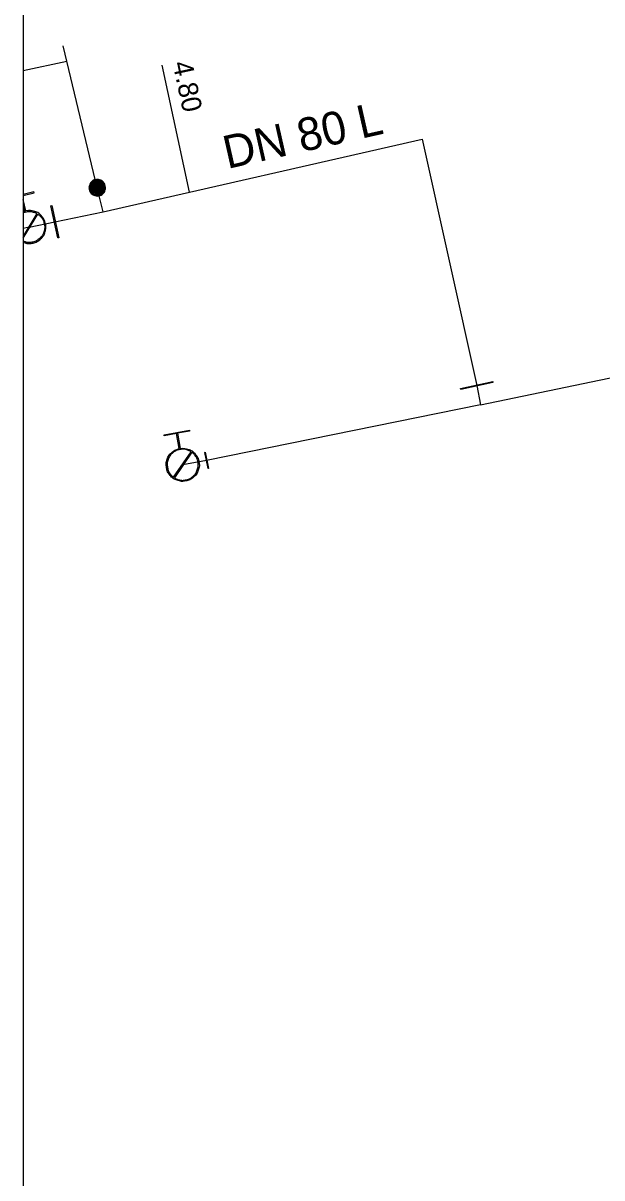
# Model space of a CAD drawing. Extents: x -820257 to -819974, y -1070894 to -1070484.
# Drawn here: x -820256.8 to -820221.7, y -1070621.8 to -1070551.7 of the extents above; entities that cross this region are included whole.
import ezdxf

# ---------------------------------------------------------------- set-up
doc = ezdxf.new("R2010")
doc.units = 0
for name, color, linetype in [('Default', 7, 'Continuous'), ('Hyd-odbočka', 7, 'Continuous'), ('Hyd-šoupě', 7, 'Continuous'), ('Hydrant', 7, 'Continuous'), ('Oměrka vodovodu', 7, 'Continuous'), ('Oměrka-text', 7, 'Continuous'), ('Přípojka vodovodu', 7, 'Continuous'), ('Přípojkový uzávěr', 7, 'Continuous'), ('Roz-řad', 7, 'Continuous'), ('Roz-řad-popis základní', 7, 'Continuous'), ('Řad-šoupě', 7, 'Continuous')]:
    doc.layers.add(name, color=color, linetype=linetype)

msp = doc.modelspace()

# ---------------------------------------------------------------- linework, layer by layer
at = {"layer": 'Default'}
msp.add_lwpolyline([(-819975.603, -1070484.403), (-820256.81, -1070484.403), (-820256.81, -1070893.932)], dxfattribs=at)
at = {"layer": 'Hyd-odbočka'}
msp.add_line((-820245.669, -1070578.217), (-820247.12, -1070578.483), dxfattribs=at)
at = {"layer": 'Hyd-šoupě'}
msp.add_lwpolyline([(-820245.752, -1070577.723), (-820245.553, -1070578.703), (-820245.584, -1070578.709), (-820245.782, -1070577.729), (-820245.752, -1070577.723)], dxfattribs=at)
at = {"layer": 'Hydrant'}
for p, q in [((-820256.81, -1070562.082), (-820256.81, -1070562.146)), ((-820256.644, -1070563.071), (-820256.81, -1070562.385)), ((-820256.81, -1070562.385), (-820256.81, -1070562.65)), ((-820256.81, -1070562.65), (-820256.704, -1070563.085)), ((-820256.81, -1070563.121), (-820256.81, -1070563.19)), ((-820255.975, -1070563.232), (-820256.81, -1070564.601)), ((-820256.81, -1070564.72), (-820255.924, -1070563.264)), ((-820256.81, -1070564.601), (-820256.81, -1070564.72)), ((-820256.81, -1070564.913), (-820256.81, -1070564.981))]:
    msp.add_line(p, q, dxfattribs=at)
for points in [[(-820256.81, -1070562.146), (-820256.136, -1070561.983), (-820256.151, -1070561.922), (-820256.81, -1070562.082)], [(-820247.332, -1070577.505), (-820247.502, -1070576.583), (-820248.239, -1070576.718), (-820248.25, -1070576.657), (-820246.714, -1070576.374), (-820246.702, -1070576.436), (-820247.44, -1070576.571), (-820247.27, -1070577.493)], [(-820247.678, -1070579.239), (-820246.612, -1070577.692)], [(-820246.562, -1070577.727), (-820247.628, -1070579.275)]]:
    msp.add_lwpolyline(points, dxfattribs=at)
for points, degree in [([(-820256.81, -1070564.981), (-820256.765, -1070564.998), (-820256.718, -1070565.011), (-820256.455, -1070565.083), (-820256.203, -1070565.022), (-820255.95, -1070564.961), (-820255.75, -1070564.776), (-820255.549, -1070564.592), (-820255.477, -1070564.329), (-820255.405, -1070564.067), (-820255.467, -1070563.814), (-820255.528, -1070563.56), (-820255.716, -1070563.358), (-820255.903, -1070563.157), (-820256.165, -1070563.087), (-820256.412, -1070563.023), (-820256.644, -1070563.071)], 3), ([(-820256.704, -1070563.085), (-820256.758, -1070563.1), (-820256.81, -1070563.121)], 2), ([(-820256.81, -1070563.19), (-820256.737, -1070563.158), (-820256.659, -1070563.139), (-820256.43, -1070563.083), (-820256.183, -1070563.148), (-820256.073, -1070563.178), (-820255.975, -1070563.232)], 3), ([(-820255.924, -1070563.264), (-820255.837, -1070563.321), (-820255.762, -1070563.401), (-820255.585, -1070563.59), (-820255.527, -1070563.829), (-820255.47, -1070564.066), (-820255.537, -1070564.312), (-820255.604, -1070564.557), (-820255.792, -1070564.73), (-820255.98, -1070564.904), (-820256.217, -1070564.961), (-820256.455, -1070565.019), (-820256.701, -1070564.95), (-820256.757, -1070564.935), (-820256.81, -1070564.913)], 3), ([(-820247.27, -1070577.493), (-820247.037, -1070577.458), (-820246.794, -1070577.537), (-820246.536, -1070577.62), (-820246.36, -1070577.832), (-820246.184, -1070578.044), (-820246.137, -1070578.302), (-820246.09, -1070578.557), (-820246.176, -1070578.815), (-820246.263, -1070579.074), (-820246.474, -1070579.246), (-820246.684, -1070579.419), (-820246.94, -1070579.466), (-820247.195, -1070579.513), (-820247.453, -1070579.426), (-820247.711, -1070579.34), (-820247.884, -1070579.129), (-820248.057, -1070578.919), (-820248.104, -1070578.663), (-820248.151, -1070578.406), (-820248.062, -1070578.145), (-820247.973, -1070577.885), (-820247.762, -1070577.715), (-820247.565, -1070577.555), (-820247.332, -1070577.505)], 3), ([(-820246.612, -1070577.692), (-820246.707, -1070577.632), (-820246.815, -1070577.596), (-820247.057, -1070577.518), (-820247.29, -1070577.561), (-820247.522, -1070577.603), (-820247.721, -1070577.763), (-820247.92, -1070577.923), (-820248.004, -1070578.166), (-820248.087, -1070578.41), (-820248.042, -1070578.652), (-820247.998, -1070578.892), (-820247.835, -1070579.089), (-820247.766, -1070579.175), (-820247.678, -1070579.239)], 3), ([(-820247.628, -1070579.275), (-820247.538, -1070579.332), (-820247.433, -1070579.366), (-820247.191, -1070579.449), (-820246.951, -1070579.405), (-820246.711, -1070579.36), (-820246.513, -1070579.198), (-820246.316, -1070579.036), (-820246.235, -1070578.794), (-820246.154, -1070578.553), (-820246.198, -1070578.313), (-820246.243, -1070578.071), (-820246.408, -1070577.873), (-820246.479, -1070577.789), (-820246.562, -1070577.727)], 3)]:
    msp.add_open_spline(points, degree=degree, dxfattribs=at)
at = {"layer": 'Oměrka vodovodu'}
for p, q in [((-820256.81, -1070554.555), (-820254.152, -1070553.993)), ((-820246.715, -1070561.929), (-820248.369, -1070554.217))]:
    msp.add_line(p, q, dxfattribs=at)
at = {"layer": 'Přípojka vodovodu'}
msp.add_lwpolyline([(-820251.957, -1070563.123), (-820252.308, -1070561.665), (-820254.38, -1070553.046)], dxfattribs=at)
at = {"layer": 'Přípojkový uzávěr'}
for points in [[(-820251.822, -1070561.548), (-820251.792, -1070561.67), (-820251.827, -1070561.802), (-820251.862, -1070561.933), (-820251.963, -1070562.027), (-820252.064, -1070562.121), (-820252.192, -1070562.152), (-820252.318, -1070562.182), (-820252.449, -1070562.146), (-820252.58, -1070562.109), (-820252.672, -1070562.009), (-820252.764, -1070561.908), (-820252.794, -1070561.782), (-820252.824, -1070561.656), (-820252.788, -1070561.525), (-820252.752, -1070561.393), (-820252.652, -1070561.301), (-820252.552, -1070561.21), (-820252.425, -1070561.179), (-820252.298, -1070561.149), (-820252.165, -1070561.186), (-820252.033, -1070561.223), (-820251.942, -1070561.324), (-820251.852, -1070561.425), (-820251.822, -1070561.548)], [(-820251.868, -1070561.559), (-820251.894, -1070561.448), (-820251.976, -1070561.356), (-820252.058, -1070561.264), (-820252.179, -1070561.231), (-820252.299, -1070561.197), (-820252.414, -1070561.225), (-820252.529, -1070561.252), (-820252.62, -1070561.335), (-820252.71, -1070561.418), (-820252.743, -1070561.538), (-820252.776, -1070561.657), (-820252.749, -1070561.771), (-820252.721, -1070561.886), (-820252.638, -1070561.977), (-820252.554, -1070562.068), (-820252.436, -1070562.101), (-820252.317, -1070562.133), (-820252.203, -1070562.106), (-820252.087, -1070562.078), (-820251.995, -1070561.993), (-820251.904, -1070561.908), (-820251.872, -1070561.789), (-820251.841, -1070561.67), (-820251.868, -1070561.559)], [(-820251.901, -1070561.567), (-820251.876, -1070561.67), (-820251.905, -1070561.78), (-820251.934, -1070561.889), (-820252.019, -1070561.968), (-820252.104, -1070562.047), (-820252.21, -1070562.073), (-820252.316, -1070562.098), (-820252.426, -1070562.068), (-820252.536, -1070562.038), (-820252.613, -1070561.953), (-820252.69, -1070561.869), (-820252.715, -1070561.763), (-820252.741, -1070561.657), (-820252.711, -1070561.547), (-820252.68, -1070561.437), (-820252.596, -1070561.36), (-820252.512, -1070561.283), (-820252.406, -1070561.258), (-820252.3, -1070561.232), (-820252.188, -1070561.263), (-820252.077, -1070561.294), (-820252.001, -1070561.379), (-820251.925, -1070561.464), (-820251.901, -1070561.567)], [(-820251.944, -1070561.577), (-820251.98, -1070561.425), (-820252.112, -1070561.345), (-820252.245, -1070561.264), (-820252.396, -1070561.301), (-820252.547, -1070561.337), (-820252.628, -1070561.47), (-820252.709, -1070561.602), (-820252.673, -1070561.752), (-820252.636, -1070561.904), (-820252.504, -1070561.985), (-820252.372, -1070562.066), (-820252.221, -1070562.03), (-820252.069, -1070561.994), (-820251.988, -1070561.862), (-820251.907, -1070561.73), (-820251.944, -1070561.577)], [(-820251.988, -1070561.587), (-820251.956, -1070561.721), (-820252.027, -1070561.836), (-820252.098, -1070561.951), (-820252.231, -1070561.983), (-820252.363, -1070562.015), (-820252.479, -1070561.944), (-820252.594, -1070561.873), (-820252.626, -1070561.741), (-820252.658, -1070561.608), (-820252.587, -1070561.492), (-820252.516, -1070561.377), (-820252.384, -1070561.345), (-820252.252, -1070561.313), (-820252.136, -1070561.384), (-820252.02, -1070561.454), (-820251.988, -1070561.587)], [(-820252.027, -1070561.597), (-820252.055, -1070561.48), (-820252.157, -1070561.418), (-820252.258, -1070561.356), (-820252.375, -1070561.383), (-820252.491, -1070561.411), (-820252.553, -1070561.513), (-820252.616, -1070561.615), (-820252.588, -1070561.732), (-820252.56, -1070561.848), (-820252.458, -1070561.91), (-820252.356, -1070561.973), (-820252.24, -1070561.945), (-820252.123, -1070561.917), (-820252.061, -1070561.815), (-820251.998, -1070561.714), (-820252.027, -1070561.597)], [(-820252.065, -1070561.606), (-820252.04, -1070561.708), (-820252.095, -1070561.796), (-820252.149, -1070561.884), (-820252.25, -1070561.908), (-820252.351, -1070561.933), (-820252.439, -1070561.878), (-820252.527, -1070561.824), (-820252.551, -1070561.723), (-820252.575, -1070561.623), (-820252.521, -1070561.535), (-820252.468, -1070561.446), (-820252.367, -1070561.422), (-820252.266, -1070561.398), (-820252.178, -1070561.451), (-820252.089, -1070561.505), (-820252.065, -1070561.606)], [(-820252.11, -1070561.617), (-820252.13, -1070561.535), (-820252.201, -1070561.491), (-820252.273, -1070561.447), (-820252.355, -1070561.467), (-820252.437, -1070561.487), (-820252.481, -1070561.558), (-820252.525, -1070561.63), (-820252.505, -1070561.712), (-820252.485, -1070561.794), (-820252.414, -1070561.838), (-820252.342, -1070561.882), (-820252.26, -1070561.862), (-820252.178, -1070561.842), (-820252.134, -1070561.771), (-820252.09, -1070561.699), (-820252.11, -1070561.617)], [(-820252.144, -1070561.625), (-820252.127, -1070561.694), (-820252.164, -1070561.753), (-820252.2, -1070561.812), (-820252.268, -1070561.828), (-820252.337, -1070561.845), (-820252.396, -1070561.808), (-820252.455, -1070561.772), (-820252.471, -1070561.704), (-820252.488, -1070561.636), (-820252.452, -1070561.576), (-820252.415, -1070561.517), (-820252.347, -1070561.501), (-820252.279, -1070561.484), (-820252.219, -1070561.521), (-820252.16, -1070561.557), (-820252.144, -1070561.625)], [(-820252.187, -1070561.636), (-820252.199, -1070561.585), (-820252.243, -1070561.558), (-820252.287, -1070561.532), (-820252.337, -1070561.544), (-820252.388, -1070561.556), (-820252.415, -1070561.6), (-820252.442, -1070561.644), (-820252.43, -1070561.694), (-820252.417, -1070561.745), (-820252.373, -1070561.772), (-820252.329, -1070561.799), (-820252.279, -1070561.787), (-820252.228, -1070561.775), (-820252.201, -1070561.731), (-820252.174, -1070561.687), (-820252.187, -1070561.636)], [(-820252.232, -1070561.647), (-820252.224, -1070561.679), (-820252.241, -1070561.706), (-820252.258, -1070561.733), (-820252.29, -1070561.741), (-820252.321, -1070561.748), (-820252.349, -1070561.732), (-820252.376, -1070561.715), (-820252.384, -1070561.683), (-820252.392, -1070561.652), (-820252.375, -1070561.624), (-820252.358, -1070561.596), (-820252.326, -1070561.589), (-820252.294, -1070561.581), (-820252.267, -1070561.598), (-820252.24, -1070561.615), (-820252.232, -1070561.647)], [(-820252.263, -1070561.654), (-820252.267, -1070561.635), (-820252.283, -1070561.625), (-820252.3, -1070561.615), (-820252.319, -1070561.619), (-820252.338, -1070561.624), (-820252.348, -1070561.64), (-820252.358, -1070561.657), (-820252.354, -1070561.676), (-820252.349, -1070561.695), (-820252.333, -1070561.705), (-820252.316, -1070561.715), (-820252.297, -1070561.71), (-820252.278, -1070561.706), (-820252.268, -1070561.689), (-820252.258, -1070561.673), (-820252.263, -1070561.654)]]:
    msp.add_open_spline(points, degree=3, dxfattribs=at)
at = {"layer": 'Roz-řad'}
for p, q in [((-820256.439, -1070564.051), (-820254.885, -1070563.733)), ((-820229.278, -1070573.675), (-820229.04, -1070574.846)), ((-820229.04, -1070574.846), (-820245.669, -1070578.217))]:
    msp.add_line(p, q, dxfattribs=at)
for points in [[(-820254.885, -1070563.733), (-820251.957, -1070563.123), (-820232.581, -1070558.71), (-820229.278, -1070573.675)], [(-820256.439, -1070564.051), (-820256.81, -1070564.141)], [(-820229.04, -1070574.846), (-820220.764, -1070573.123), (-820201.308, -1070569.092), (-820198.316, -1070583.473)]]:
    msp.add_lwpolyline(points, dxfattribs=at)
at = {"layer": 'Řad-šoupě'}
for points in [[(-820255.057, -1070562.747), (-820254.649, -1070564.705), (-820254.711, -1070564.717), (-820255.118, -1070562.76), (-820255.057, -1070562.747)], [(-820228.295, -1070573.49), (-820230.248, -1070573.921), (-820230.261, -1070573.86), (-820228.308, -1070573.429), (-820228.295, -1070573.49)]]:
    msp.add_lwpolyline(points, dxfattribs=at)

# ---------------------------------------------------------------- texts
at = {"layer": 'Oměrka-text'}
msp.add_text(' 4.80', height=1.2, rotation=282.10488, dxfattribs=at).set_placement((-820247.834, -1070553.67))
at = {"layer": 'Roz-řad-popis základní'}
msp.add_text('DN 80 L', height=2, rotation=12.74218, dxfattribs=at).set_placement((-820244.41, -1070560.532))

doc.saveas('drawing.dxf')
